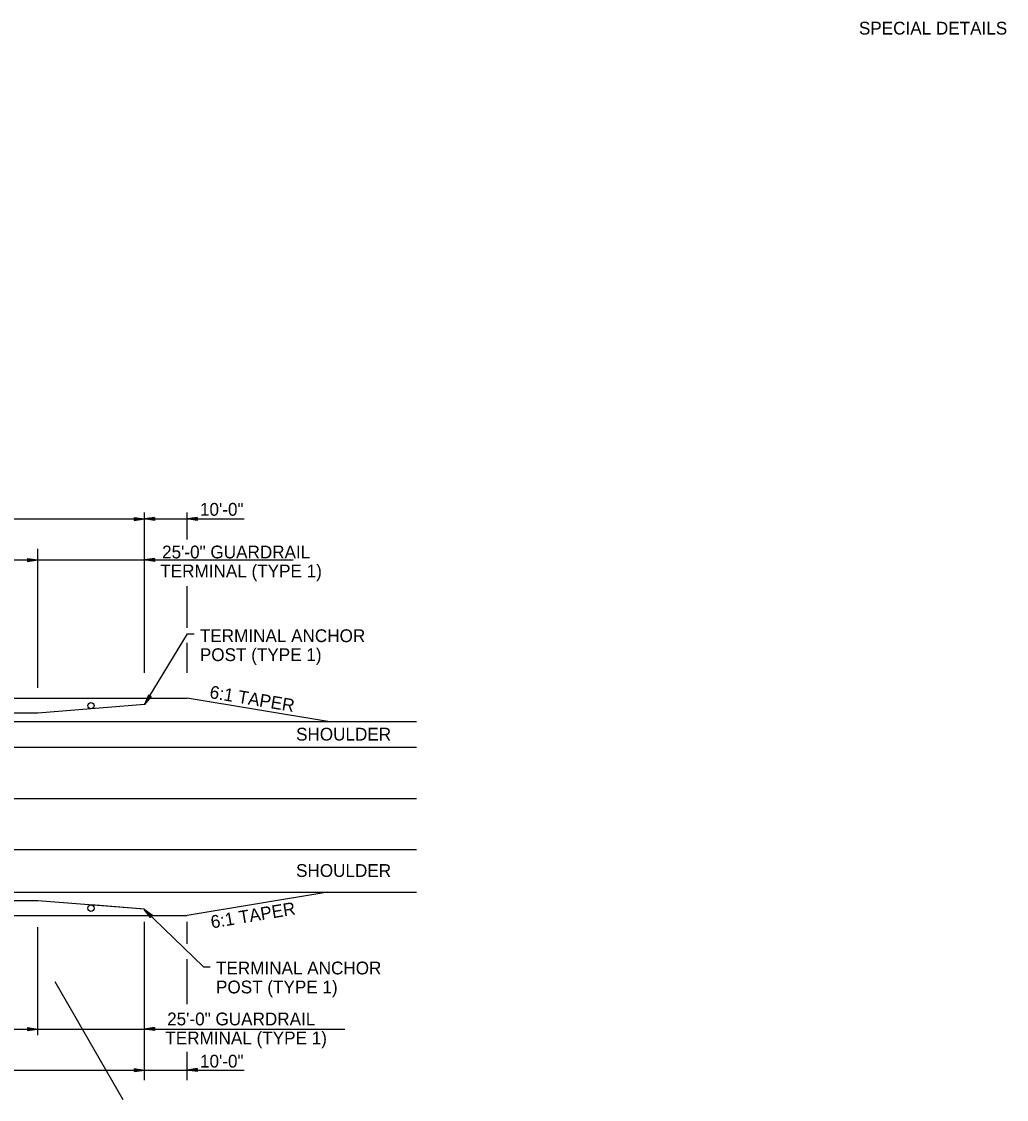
# Model space of a CAD drawing. Extents: x 1373853 to 1374003, y 380191 to 380927.
# Drawn here: x 1373952.4 to 1373998.6, y 380876.3 to 380926.8 of the extents above; entities that cross this region are included whole.
import ezdxf

# ---------------------------------------------------------------- set-up
doc = ezdxf.new("R2010")
doc.units = 0
for name, color, linetype in [('2', 7, 'Continuous'), ('44', 7, 'Continuous'), ('7', 7, 'Continuous'), ('E_Existing ROW', 7, 'Continuous'), ('G-ANNO-TEXT', 7, 'Continuous'), ('R_Proposed Road', 7, 'Continuous')]:
    doc.layers.add(name, color=color, linetype=linetype)

msp = doc.modelspace()

# ---------------------------------------------------------------- linework, layer by layer
at = {"layer": '2'}
for p, q in [((1373958.176, 380896.276), (1373958.176, 380903.795)), ((1373960.176, 380902.541), (1373960.176, 380903.795)), ((1373888.075, 380903.499), (1373962.85, 380903.499)), ((1373953.176, 380895.569), (1373953.176, 380902.098)), ((1373903.184, 380901.577), (1373965.149, 380901.575)), ((1373960.176, 380898.394), (1373960.176, 380900.342)), ((1373958.176, 380894.791), (1373960.192, 380898.103)), ((1373960.192, 380898.103), (1373960.511, 380898.103)), ((1373960.176, 380896.276), (1373960.176, 380897.692)), ((1373958.168, 380885.186), (1373960.948, 380882.483)), ((1373953.176, 380879.283), (1373953.176, 380884.35)), ((1373958.176, 380877.168), (1373958.176, 380884.593)), ((1373960.176, 380883.571), (1373960.176, 380884.593)), ((1373960.176, 380880.742), (1373960.176, 380882.846)), ((1373960.948, 380882.483), (1373961.267, 380882.483)), ((1373903.176, 380879.572), (1373967.577, 380879.572)), ((1373960.176, 380877.168), (1373960.176, 380878.496)), ((1373888.057, 380877.648), (1373962.85, 380877.648))]:
    msp.add_line(p, q, dxfattribs=at)
at = {"layer": '44'}
for p, q in [((1373877.32, 380893.991), (1373970.938, 380893.991)), ((1373877.32, 380885.991), (1373970.938, 380885.991))]:
    msp.add_line(p, q, dxfattribs=at)
at = {"layer": '7'}
for p, q in [((1373957.696, 380903.573), (1373958.176, 380903.499)), ((1373957.696, 380903.573), (1373957.696, 380903.427)), ((1373957.696, 380903.559), (1373958.094, 380903.499)), ((1373957.696, 380903.547), (1373958.013, 380903.499)), ((1373957.696, 380903.535), (1373957.932, 380903.499)), ((1373957.696, 380903.523), (1373957.853, 380903.499)), ((1373957.696, 380903.511), (1373957.772, 380903.499)), ((1373958.656, 380903.573), (1373958.176, 380903.499)), ((1373958.656, 380903.559), (1373958.257, 380903.499)), ((1373958.656, 380903.547), (1373958.338, 380903.499)), ((1373958.656, 380903.535), (1373958.419, 380903.499)), ((1373958.656, 380903.523), (1373958.498, 380903.499)), ((1373958.656, 380903.511), (1373958.579, 380903.499)), ((1373958.656, 380903.573), (1373958.656, 380903.427)), ((1373960.656, 380903.573), (1373960.176, 380903.499)), ((1373960.656, 380903.559), (1373960.257, 380903.499)), ((1373960.656, 380903.547), (1373960.338, 380903.499)), ((1373960.656, 380903.535), (1373960.419, 380903.499)), ((1373960.656, 380903.523), (1373960.498, 380903.499)), ((1373960.656, 380903.511), (1373960.579, 380903.499)), ((1373960.656, 380903.573), (1373960.656, 380903.427)), ((1373957.696, 380903.427), (1373958.176, 380903.499)), ((1373957.696, 380903.478), (1373957.853, 380903.499)), ((1373957.696, 380903.454), (1373958.013, 380903.499)), ((1373957.696, 380903.439), (1373958.094, 380903.499)), ((1373957.696, 380903.463), (1373957.932, 380903.499)), ((1373957.696, 380903.49), (1373957.772, 380903.499)), ((1373958.656, 380903.427), (1373958.176, 380903.499)), ((1373958.656, 380903.439), (1373958.257, 380903.499)), ((1373958.656, 380903.454), (1373958.338, 380903.499)), ((1373958.656, 380903.463), (1373958.419, 380903.499)), ((1373958.656, 380903.478), (1373958.498, 380903.499)), ((1373958.656, 380903.49), (1373958.579, 380903.499)), ((1373960.656, 380903.427), (1373960.176, 380903.499)), ((1373960.656, 380903.439), (1373960.257, 380903.499)), ((1373960.656, 380903.454), (1373960.338, 380903.499)), ((1373960.656, 380903.463), (1373960.419, 380903.499)), ((1373960.656, 380903.478), (1373960.498, 380903.499)), ((1373960.656, 380903.49), (1373960.579, 380903.499)), ((1373952.696, 380901.649), (1373953.176, 380901.575)), ((1373952.696, 380901.649), (1373952.696, 380901.503)), ((1373952.696, 380901.634), (1373953.094, 380901.575)), ((1373952.696, 380901.622), (1373953.013, 380901.575)), ((1373952.696, 380901.61), (1373952.932, 380901.575)), ((1373952.696, 380901.599), (1373952.853, 380901.575)), ((1373952.696, 380901.587), (1373952.772, 380901.575)), ((1373952.696, 380901.503), (1373953.176, 380901.575)), ((1373952.696, 380901.553), (1373952.853, 380901.575)), ((1373952.696, 380901.529), (1373953.013, 380901.575)), ((1373952.696, 380901.515), (1373953.094, 380901.575)), ((1373952.696, 380901.539), (1373952.932, 380901.575)), ((1373952.696, 380901.565), (1373952.772, 380901.575)), ((1373958.656, 380901.649), (1373958.176, 380901.575)), ((1373958.656, 380901.503), (1373958.176, 380901.575)), ((1373958.656, 380901.634), (1373958.257, 380901.575)), ((1373958.656, 380901.515), (1373958.257, 380901.575)), ((1373958.656, 380901.622), (1373958.338, 380901.575)), ((1373958.656, 380901.529), (1373958.338, 380901.575)), ((1373958.656, 380901.61), (1373958.419, 380901.575)), ((1373958.656, 380901.539), (1373958.419, 380901.575)), ((1373958.656, 380901.599), (1373958.498, 380901.575)), ((1373958.656, 380901.553), (1373958.498, 380901.575)), ((1373958.656, 380901.587), (1373958.579, 380901.575)), ((1373958.656, 380901.565), (1373958.579, 380901.575)), ((1373958.656, 380901.649), (1373958.656, 380901.503)), ((1373958.365, 380895.236), (1373958.176, 380894.791)), ((1373958.488, 380895.163), (1373958.176, 380894.791)), ((1373958.377, 380895.232), (1373958.219, 380894.858)), ((1373958.479, 380895.168), (1373958.219, 380894.858)), ((1373958.39, 380895.224), (1373958.263, 380894.93)), ((1373958.466, 380895.174), (1373958.263, 380894.93)), ((1373958.397, 380895.216), (1373958.304, 380894.997)), ((1373958.457, 380895.18), (1373958.304, 380894.997)), ((1373958.406, 380895.212), (1373958.344, 380895.065)), ((1373958.445, 380895.187), (1373958.344, 380895.065)), ((1373958.488, 380895.163), (1373958.365, 380895.236)), ((1373958.416, 380895.205), (1373958.389, 380895.135)), ((1373958.436, 380895.196), (1373958.389, 380895.135)), ((1373958.563, 380884.904), (1373958.168, 380885.186)), ((1373958.463, 380884.803), (1373958.168, 380885.186)), ((1373958.556, 380884.897), (1373958.227, 380885.132)), ((1373958.473, 380884.809), (1373958.227, 380885.132)), ((1373958.483, 380884.82), (1373958.287, 380885.073)), ((1373958.545, 380884.888), (1373958.287, 380885.073)), ((1373958.538, 380884.879), (1373958.344, 380885.019)), ((1373958.489, 380884.83), (1373958.344, 380885.019)), ((1373958.496, 380884.836), (1373958.4, 380884.962)), ((1373958.527, 380884.87), (1373958.4, 380884.962)), ((1373958.504, 380884.845), (1373958.46, 380884.906)), ((1373958.522, 380884.859), (1373958.46, 380884.906)), ((1373958.563, 380884.904), (1373958.463, 380884.803)), ((1373952.696, 380879.646), (1373953.176, 380879.572)), ((1373952.696, 380879.646), (1373952.696, 380879.5)), ((1373952.696, 380879.632), (1373953.094, 380879.572)), ((1373952.696, 380879.62), (1373953.013, 380879.572)), ((1373952.696, 380879.608), (1373952.932, 380879.572)), ((1373952.696, 380879.596), (1373952.853, 380879.572)), ((1373952.696, 380879.584), (1373952.772, 380879.572)), ((1373952.696, 380879.5), (1373953.176, 380879.572)), ((1373952.696, 380879.551), (1373952.853, 380879.572)), ((1373952.696, 380879.527), (1373953.013, 380879.572)), ((1373952.696, 380879.512), (1373953.094, 380879.572)), ((1373952.696, 380879.536), (1373952.932, 380879.572)), ((1373952.696, 380879.562), (1373952.772, 380879.572)), ((1373958.656, 380879.646), (1373958.176, 380879.572)), ((1373958.656, 380879.5), (1373958.176, 380879.572)), ((1373958.656, 380879.632), (1373958.257, 380879.572)), ((1373958.656, 380879.512), (1373958.257, 380879.572)), ((1373958.656, 380879.62), (1373958.338, 380879.572)), ((1373958.656, 380879.527), (1373958.338, 380879.572)), ((1373958.656, 380879.608), (1373958.419, 380879.572)), ((1373958.656, 380879.536), (1373958.419, 380879.572)), ((1373958.656, 380879.596), (1373958.498, 380879.572)), ((1373958.656, 380879.551), (1373958.498, 380879.572)), ((1373958.656, 380879.584), (1373958.579, 380879.572)), ((1373958.656, 380879.562), (1373958.579, 380879.572)), ((1373958.656, 380879.646), (1373958.656, 380879.5)), ((1373957.696, 380877.722), (1373958.176, 380877.648)), ((1373957.696, 380877.722), (1373957.696, 380877.576)), ((1373960.656, 380877.722), (1373960.176, 380877.648)), ((1373960.656, 380877.722), (1373960.656, 380877.576)), ((1373957.696, 380877.707), (1373958.094, 380877.648)), ((1373957.696, 380877.695), (1373958.013, 380877.648)), ((1373957.696, 380877.683), (1373957.932, 380877.648)), ((1373957.696, 380877.671), (1373957.853, 380877.648)), ((1373957.696, 380877.66), (1373957.772, 380877.648)), ((1373957.696, 380877.576), (1373958.176, 380877.648)), ((1373957.696, 380877.626), (1373957.853, 380877.648)), ((1373957.696, 380877.602), (1373958.013, 380877.648)), ((1373957.696, 380877.588), (1373958.094, 380877.648)), ((1373957.696, 380877.612), (1373957.932, 380877.648)), ((1373957.696, 380877.638), (1373957.772, 380877.648)), ((1373960.656, 380877.576), (1373960.176, 380877.648)), ((1373960.656, 380877.707), (1373960.257, 380877.648)), ((1373960.656, 380877.588), (1373960.257, 380877.648)), ((1373960.656, 380877.695), (1373960.338, 380877.648)), ((1373960.656, 380877.602), (1373960.338, 380877.648)), ((1373960.656, 380877.683), (1373960.419, 380877.648)), ((1373960.656, 380877.612), (1373960.419, 380877.648)), ((1373960.656, 380877.671), (1373960.498, 380877.648)), ((1373960.656, 380877.626), (1373960.498, 380877.648)), ((1373960.656, 380877.66), (1373960.579, 380877.648)), ((1373960.656, 380877.638), (1373960.579, 380877.648))]:
    msp.add_line(p, q, dxfattribs=at)
at = {"layer": 'E_Existing ROW'}
msp.add_lwpolyline([(1373953.976, 380881.805), (1373957.172, 380876.269)], dxfattribs=at)
at = {"layer": 'R_Proposed Road'}
for p, q in [((1373966.776, 380893.991), (1373960.176, 380895.091)), ((1373877.32, 380892.791), (1373970.938, 380892.791)), ((1373877.32, 380890.391), (1373970.938, 380890.391)), ((1373877.32, 380887.991), (1373970.938, 380887.991)), ((1373966.776, 380885.991), (1373960.176, 380884.891))]:
    msp.add_line(p, q, dxfattribs=at)
for points in [[(1373933.183, 380895.091), (1373960.176, 380895.091)], [(1373958.176, 380894.791), (1373953.176, 380894.391), (1373940.692, 380894.391)], [(1373958.176, 380894.791), (1373955.684, 380894.591)], [(1373958.176, 380885.191), (1373953.176, 380885.591), (1373940.692, 380885.591)], [(1373958.176, 380885.191), (1373955.684, 380885.39)], [(1373933.183, 380884.891), (1373960.176, 380884.891)]]:
    msp.add_lwpolyline(points, dxfattribs=at)
for centre in [(1373955.672, 380894.74), (1373955.672, 380885.241)]:
    msp.add_circle(centre, 0.15, dxfattribs=at)

# ---------------------------------------------------------------- texts
at = {"layer": '2'}
for s, rotation, p in [('10\'-0"', 0, (1373960.784, 380903.649)), ('25\'-0" GUARDRAIL', 0, (1373959.007, 380901.648)), ('TERMINAL (TYPE 1)', 0, (1373958.922, 380900.758)), ('TERMINAL ANCHOR', 0, (1373960.779, 380897.721)), ('POST (TYPE 1)', 0, (1373960.779, 380896.831)), ('6:1 TAPER', 350.5377, (1373961.205, 380895.1)), ('SHOULDER', 0, (1373965.29, 380893.103)), ('SHOULDER', 0, (1373965.29, 380886.707)), ('6:1 TAPER', 9.4623, (1373961.339, 380884.288)), ('TERMINAL ANCHOR', 0, (1373961.535, 380882.134)), ('POST (TYPE 1)', 0, (1373961.535, 380881.244)), ('25\'-0" GUARDRAIL', 0, (1373959.244, 380879.744)), ('TERMINAL (TYPE 1)', 0, (1373959.159, 380878.854)), ('10\'-0"', 0, (1373960.785, 380877.765))]:
    msp.add_text(s, height=0.6, rotation=rotation, dxfattribs=at).set_placement(p)
at = {"layer": 'G-ANNO-TEXT'}
msp.add_text('SPECIAL DETAILS', height=0.6, dxfattribs=at).set_placement((1373991.689, 380926.22))

doc.saveas('drawing.dxf')
